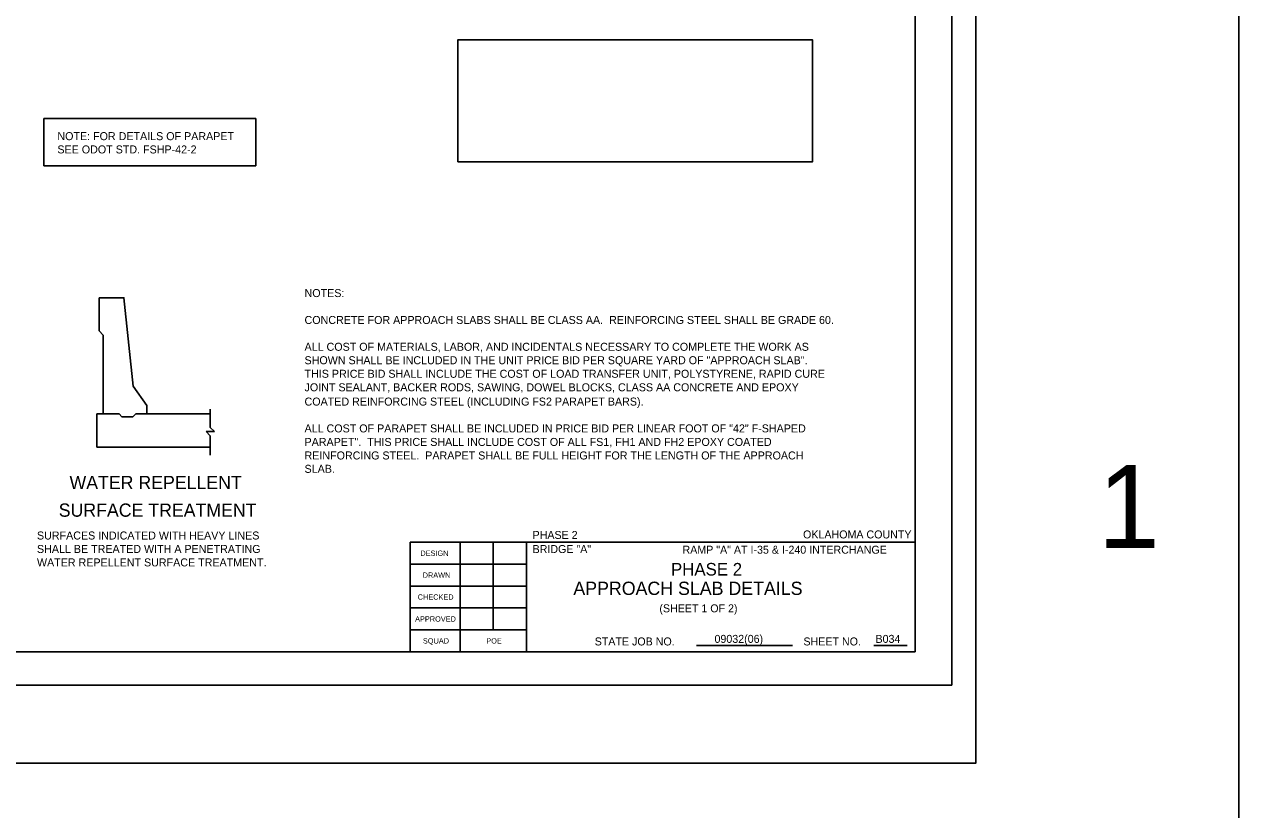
# Model space of a CAD drawing. Extents: x 570 to 2152770, y 726 to 141756.
# Drawn here: x 2151386 to 2151532.2, y 141472 to 141566.6 of the extents above; entities that cross this region are included whole.
import ezdxf

# ---------------------------------------------------------------- set-up
doc = ezdxf.new("R2010")
doc.units = 0
for name, color, linetype in [('4', 7, 'Continuous'), ('5', 7, 'Continuous'), ('6', 7, 'Continuous'), ('8', 7, 'Continuous'), ('Default', 7, 'Continuous'), ('S', 7, 'Continuous'), ('SHT_Plot_Shape_Full', 7, 'Continuous'), ('SHT_Plot_Shape_Half', 7, 'Continuous'), ('SHT_Sheet_Border', 7, 'Continuous'), ('SHT_Standard_Sheet_Lines', 7, 'Continuous'), ('SHT_Standard_Sheet_Txt', 7, 'Continuous'), ('T', 7, 'Continuous'), ('T-Title', 7, 'Continuous')]:
    doc.layers.add(name, color=color, linetype=linetype)

# ---------------------------------------------------------------- blocks, each defined once
blk = doc.blocks.new('DWG01008_2')
at = {"layer": 'Default'}
for p, q in [((-0.0132, 0), (0, 0.0132)), ((0, 0.0132), (0, -0.0132)), ((0, -0.0132), (0.0132, 0))]:
    blk.add_line(p, q, dxfattribs=at)

msp = doc.modelspace()

# ---------------------------------------------------------------- linework, layer by layer
at = {"layer": '5'}
msp.add_lwpolyline([(2151400.74, 141519.7), (2151400.74, 141520.7), (2151399.11, 141523.03), (2151397.99, 141533.7), (2151394.99, 141533.7)], dxfattribs=at)
at = {"layer": '6'}
for p, q in [((2151394.99, 141529.7), (2151394.99, 141533.7)), ((2151394.99, 141529.7), (2151395.49, 141529.2)), ((2151395.49, 141519.7), (2151395.49, 141529.2)), ((2151395.41, 141519.7), (2151394.74, 141519.7)), ((2151394.74, 141519.7), (2151394.74, 141515.7)), ((2151395.41, 141519.7), (2151397.41, 141519.7)), ((2151397.41, 141519.7), (2151397.74, 141519.37)), ((2151397.74, 141519.37), (2151399.07, 141519.37)), ((2151399.41, 141519.7), (2151399.07, 141519.37)), ((2151399.41, 141519.7), (2151408.38, 141519.7)), ((2151408.38, 141518.08), (2151408.38, 141520.26)), ((2151408.38, 141514.75), (2151408.38, 141517.08)), ((2151394.74, 141515.7), (2151408.38, 141515.7))]:
    msp.add_line(p, q, dxfattribs=at)
at = {"layer": '8'}
msp.add_lwpolyline([(2151191.03, 141756.43), (2151532.18, 141756.43), (2151532.18, 141194.31), (2151191.03, 141194.31)], close=True, dxfattribs=at)
at = {"layer": 'Defpoints'}
msp.add_lwpolyline([(2151438.18, 141550.07), (2151480.89, 141550.07), (2151480.89, 141564.75), (2151438.18, 141564.75)], close=True, dxfattribs=at)
at = {"layer": 'SHT_Plot_Shape_Full'}
msp.add_lwpolyline([(2151212.55, 141669.65), (2151500.55, 141669.65), (2151500.55, 141477.65), (2151212.55, 141477.65)], close=True, dxfattribs=at)
at = {"layer": 'SHT_Plot_Shape_Half'}
msp.add_lwpolyline([(2151225.65, 141663.05), (2151497.65, 141663.05), (2151497.65, 141487.05), (2151225.65, 141487.05)], close=True, dxfattribs=at)
at = {"layer": 'SHT_Sheet_Border'}
for p, q in [((2151432.45, 141491.05), (2151432.45, 141504.25)), ((2151432.45, 141504.25), (2151493.25, 141504.25)), ((2151446.45, 141491.05), (2151446.45, 141504.26)), ((2151446.45, 141491.05), (2151446.45, 141504.26))]:
    msp.add_line(p, q, dxfattribs=at)
msp.add_lwpolyline([(2151493.25, 141491.05), (2151241.25, 141491.05), (2151241.25, 141659.05), (2151493.25, 141659.05)], close=True, dxfattribs=at)
at = {"layer": 'SHT_Standard_Sheet_Lines'}
for p, q in [((2151438.45, 141491.05), (2151438.45, 141504.26)), ((2151442.45, 141493.69), (2151442.45, 141504.26)), ((2151466.93, 141491.82), (2151478.46, 141491.82)), ((2151466.93, 141491.82), (2151478.46, 141491.82)), ((2151488.25, 141491.82), (2151492.27, 141491.82)), ((2151488.25, 141491.82), (2151492.27, 141491.82))]:
    msp.add_line(p, q, dxfattribs=at)
for points in [[(2151446.45, 141501.61), (2151432.45, 141501.61)], [(2151446.45, 141498.97), (2151432.45, 141498.97)], [(2151446.45, 141496.33), (2151432.45, 141496.33)], [(2151446.45, 141493.69), (2151432.45, 141493.69)]]:
    msp.add_lwpolyline(points, dxfattribs=at)
at = {"layer": 'T'}
for p, q in [((2151413.85, 141555.27), (2151388.33, 141555.27)), ((2151388.33, 141555.27), (2151388.33, 141549.57)), ((2151413.85, 141549.57), (2151413.85, 141555.27)), ((2151413.85, 141549.6), (2151388.33, 141549.6))]:
    msp.add_line(p, q, dxfattribs=at)

# ---------------------------------------------------------------- block references
at = {"layer": '6', "xscale": 37.78306610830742, "yscale": 37.78306610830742, "rotation": 90}
msp.add_blockref('DWG01008_2', (2151408.38, 141517.58), dxfattribs=at)

# ---------------------------------------------------------------- texts
at = {"layer": '4'}
for s, p in [('WATER REPELLENT', (2151391.44, 141510.65)), ('SURFACE TREATMENT', (2151390.14, 141507.32))]:
    msp.add_text(s, height=1.5946, dxfattribs=at).set_placement(p)
at = {"layer": 'Defpoints'}
msp.add_text('PHASE 2', height=1.516, dxfattribs=at).set_placement((2151463.84, 141500.24))
at = {"layer": 'S'}
msp.add_text('1', height=10, dxfattribs=at).set_placement((2151515.23, 141503.57))
at = {"layer": 'SHT_Standard_Sheet_Txt'}
for s, height, p in [('DESIGN', 0.64, (2151433.67, 141502.61)), ('DRAWN', 0.64, (2151433.95, 141499.97)), ('CHECKED', 0.64, (2151433.35, 141497.33)), ('APPROVED', 0.64, (2151433.04, 141494.69)), ('SQUAD', 0.64, (2151433.98, 141492.05)), ('POE', 0.64, (2151441.61, 141492.05)), ('STATE JOB NO.', 0.96, (2151454.66, 141491.82)), ('STATE JOB NO.', 0.96, (2151454.66, 141491.82)), ('SHEET NO. ', 0.96, (2151479.79, 141491.82)), ('SHEET NO. ', 0.96, (2151479.79, 141491.82))]:
    msp.add_text(s, height=height, dxfattribs=at).set_placement(p)
at = {"layer": 'T'}
for s, height, p in [('NOTE: FOR DETAILS OF PARAPET', 0.9635, (2151389.98, 141552.68)), ('SEE ODOT STD. FSHP-42-2', 0.9635, (2151389.98, 141551.08)), ('NOTES:', 0.964, (2151419.73, 141533.78)), ('CONCRETE FOR APPROACH SLABS SHALL BE CLASS AA.  REINFORCING STEEL SHALL BE GRADE 60.', 0.9635, (2151419.73, 141530.54)), ('ALL COST OF MATERIALS, LABOR, AND INCIDENTALS NECESSARY TO COMPLETE THE WORK AS ', 0.9635, (2151419.73, 141527.31)), ('SHOWN SHALL BE INCLUDED IN THE UNIT PRICE BID PER SQUARE YARD OF "APPROACH SLAB".  ', 0.9635, (2151419.73, 141525.69)), ('THIS PRICE BID SHALL INCLUDE THE COST OF LOAD TRANSFER UNIT, POLYSTYRENE, RAPID CURE ', 0.9635, (2151419.73, 141524.06)), ('JOINT SEALANT, BACKER RODS, SAWING, DOWEL BLOCKS, CLASS AA CONCRETE AND EPOXY ', 0.9635, (2151419.73, 141522.43)), ('COATED REINFORCING STEEL (INCLUDING FS2 PARAPET BARS).', 0.9635, (2151419.73, 141520.71)), ('ALL COST OF PARAPET SHALL BE INCLUDED IN PRICE BID PER LINEAR FOOT OF "42" F-SHAPED ', 0.9635, (2151419.73, 141517.48)), ('PARAPET".  THIS PRICE SHALL INCLUDE COST OF ALL FS1, FH1 AND FH2 EPOXY COATED ', 0.9635, (2151419.73, 141515.85)), ('REINFORCING STEEL.  PARAPET SHALL BE FULL HEIGHT FOR THE LENGTH OF THE APPROACH ', 0.9635, (2151419.73, 141514.22)), ('SLAB.', 0.964, (2151419.73, 141512.61)), ('SURFACES INDICATED WITH HEAVY LINES ', 0.9635, (2151387.52, 141504.58)), ('PHASE 2', 0.96, (2151447.18, 141504.65)), ('OKLAHOMA COUNTY', 0.96, (2151479.74, 141504.71)), ('SHALL BE TREATED WITH A PENETRATING ', 0.9635, (2151387.52, 141502.96)), ('BRIDGE "A"', 0.96, (2151447.18, 141502.95)), ('RAMP "A" AT I-35 & I-240 INTERCHANGE', 0.96, (2151465.23, 141502.87)), ('WATER REPELLENT SURFACE TREATMENT.', 0.9635, (2151387.52, 141501.34)), ('(SHEET 1 OF 2)', 0.9583, (2151462.45, 141495.81)), ('09032(06)', 0.96, (2151469.08, 141492.13)), ('B034', 0.96, (2151488.46, 141492.13))]:
    msp.add_text(s, height=height, dxfattribs=at).set_placement(p)
at = {"layer": 'T-Title'}
msp.add_text('APPROACH SLAB DETAILS', height=1.6, dxfattribs=at).set_placement((2151452.09, 141497.9))

doc.saveas('drawing.dxf')
